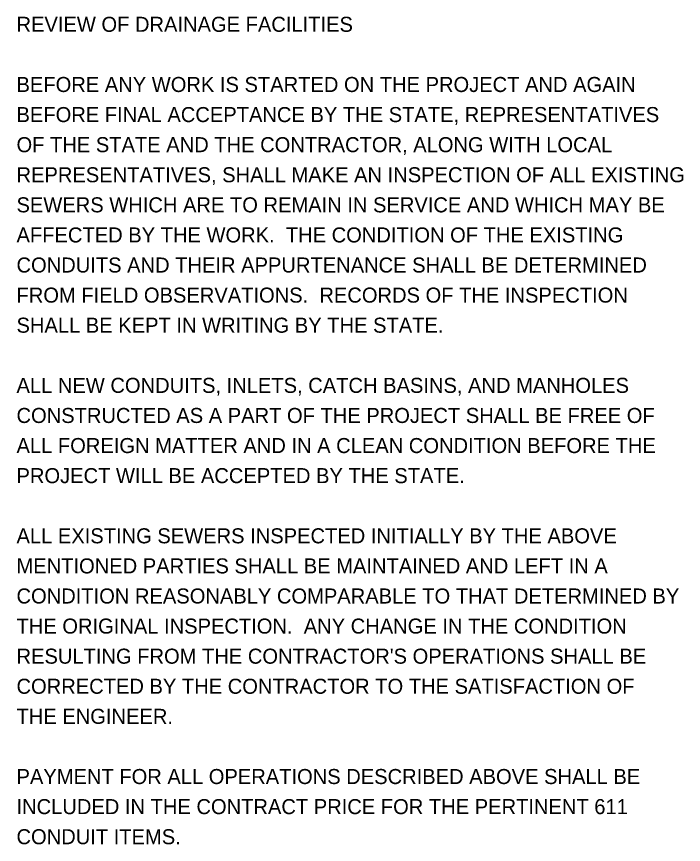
# Model space of a CAD drawing. Extents: x 0 to 58.9, y -9.9 to 22.
# Drawn here: x 52.68 to 58.89, y -9.9 to -2.2 of the extents above; entities that cross this region are included whole.
import ezdxf

# ---------------------------------------------------------------- set-up
doc = ezdxf.new("R2010")
doc.units = 0
doc.layers.add('SH_Text', color=7, linetype='Continuous')

msp = doc.modelspace()

# ---------------------------------------------------------------- texts
at = {"layer": 'SH_Text'}
for s, p in [('REVIEW OF DRAINAGE FACILITIES', (52.6809, -2.343)), ('BEFORE ANY WORK IS STARTED ON THE PROJECT AND AGAIN', (52.6809, -2.903)), ('BEFORE FINAL ACCEPTANCE BY THE STATE, REPRESENTATIVES', (52.6809, -3.183)), ('OF THE STATE AND THE CONTRACTOR, ALONG WITH LOCAL', (52.6809, -3.463)), ('REPRESENTATIVES, SHALL MAKE AN INSPECTION OF ALL EXISTING', (52.6809, -3.743)), ('SEWERS WHICH ARE TO REMAIN IN SERVICE AND WHICH MAY BE', (52.6809, -4.023)), ('AFFECTED BY THE WORK.  THE CONDITION OF THE EXISTING', (52.6809, -4.303)), ('CONDUITS AND THEIR APPURTENANCE SHALL BE DETERMINED', (52.6809, -4.583)), ('FROM FIELD OBSERVATIONS.  RECORDS OF THE INSPECTION', (52.6809, -4.863)), ('SHALL BE KEPT IN WRITING BY THE STATE.', (52.6809, -5.143)), ('ALL NEW CONDUITS, INLETS, CATCH BASINS, AND MANHOLES', (52.6809, -5.703)), ('CONSTRUCTED AS A PART OF THE PROJECT SHALL BE FREE OF', (52.6809, -5.983)), ('ALL FOREIGN MATTER AND IN A CLEAN CONDITION BEFORE THE', (52.6809, -6.263)), ('PROJECT WILL BE ACCEPTED BY THE STATE.', (52.6809, -6.543)), ('ALL EXISTING SEWERS INSPECTED INITIALLY BY THE ABOVE', (52.6809, -7.103)), ('MENTIONED PARTIES SHALL BE MAINTAINED AND LEFT IN A', (52.6809, -7.383)), ('CONDITION REASONABLY COMPARABLE TO THAT DETERMINED BY', (52.6809, -7.663)), ('THE ORIGINAL INSPECTION.  ANY CHANGE IN THE CONDITION', (52.6809, -7.943)), ("RESULTING FROM THE CONTRACTOR'S OPERATIONS SHALL BE", (52.6809, -8.223)), ('CORRECTED BY THE CONTRACTOR TO THE SATISFACTION OF', (52.6809, -8.503)), ('THE ENGINEER.', (52.6809, -8.783)), ('PAYMENT FOR ALL OPERATIONS DESCRIBED ABOVE SHALL BE', (52.6809, -9.343)), ('INCLUDED IN THE CONTRACT PRICE FOR THE PERTINENT 611', (52.6809, -9.623)), ('CONDUIT ITEMS.', (52.6809, -9.903))]:
    msp.add_text(s, height=0.14, dxfattribs=at).set_placement(p)

doc.saveas('drawing.dxf')
